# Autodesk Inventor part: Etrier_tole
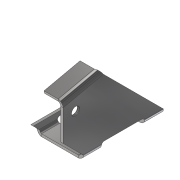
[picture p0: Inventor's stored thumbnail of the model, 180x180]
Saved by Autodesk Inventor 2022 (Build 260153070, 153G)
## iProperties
Created: 2018-06
Part Number: Etrier_tole
Material: Acier inoxydable
Document SubType Name: Tôle
Designer: Fabian Perrée
Density: 8 g/cm^3
Sheet Metal Rule: Par défaut_mm
Appearance: Semi-poli
Flat Pattern Width: 6.40181 cm
Flat Pattern Length: 9.4026 cm
Flat Pattern Area: 60.1936 cm^2
Sheet Metal Width: 64,018 mm
Sheet Metal Length: 94,026 mm
Sheet Metal Area: 6019,365 mm^2
Mass: 45.3586 g
Surface Area: 83.174 cm^2
Volume: 5.66982 cm^3
Author: Fabian Perrée
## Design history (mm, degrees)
node "Face1"
  sketch "Esquisse1"
    geometry: L1 (-12.5, 24)-(12.5, 24); L2 (12.5, 24)-(12.5, -24); L3 (12.5, -24)-(-12.5, -24); L4 (-12.5, -24)-(-12.5, 24); L5 (-12.5, 24)-(12.5, -24); L6 (12.5, 24)-(-12.5, -24); C1 r 3 at (0, 18.5); C2 r 3 at (0, -18.5); 3 further points
    constraints: 12 end point, 4 midpoint, 2 centre point, 2 parallel, 2 vertical alignment, 1 equal radius, 1 horizontal, 1 perpendicular
    dimensions: "d0" = 25 distance of L2.end L3.end; "d1" = 48 distance of L1.end L2.end; "d31" = 5.5 distance from line of L1 C1.centre (= d43); "d32" = 6 diameter of C1; "d43" = 5.5 distance from line of L3 C2.centre
node "Face2"
  sketch "Esquisse2"
    geometry: L1 (0, 0)-(0, 1.5) reference; L2 (48, 0)-(0, 0) reference; L3 (48, 0)-(48, 1.5) reference; L4 (0, 1.5)-(0, 3); L5 (0, 3)-(-12, 15); L6 (-12, 15)-(-12, 36.58); L7 (7, 3.333)-(7, -2.476); L8 (-12, 36.58)-(9.626, 41.374); L9 (48, 1.5)-(48, 3); L10 (48, 3)-(9.626, 41.374); C1 r 2.5 at (-4.5, 28); 2 further points
    constraints: 14 end point, 3 vertical, 1 centre point, 1 coincident, 1 parallel
    dimensions: "d3" = 3 distance from line of L2 L4.end; "d6" = 45 deg angle of L5 L6; "d7" = 28 distance from line of L2 point (-4.5, 28); "d8" = 7 distance between parallel lines of L4 L7; "d9" = 11.5 distance from line of point (-4.5, 28) L7; "d10" = 10 distance from line of point (-4.5, 28) L8; "d11" = 12.5 deg angle of L2 L8; "d12" = 3 distance from line of L2 L9.end; "d13" = 45 deg angle of L2 L10; "d14" = 5 diameter of C1; "d40" = 12 horizontal distance of L5.end L4.end
mirror "Symétrie1"
node "Bord tombé1"
sketch "Esquisse4"
  geometry: L1 (0, 0)-(48, 0) reference; L2 (11, 0)-(37, 0); L3 (37, 0)-(37, 2.5); L4 (35.5, 4)-(12.5, 4); L5 (11, 2.5)-(11, 0); L6 (2.5, 1.5)-(8.5, 1.5) reference; L7 (8.5, 0)-(2.5, 0) reference; L8 (0, 1.5)-(48, 1.5) reference; L9 (8.5, 0)-(2.5, 0) reference; L10 (45.5, 0)-(39.5, 0) reference; L11 (5.5, 0)-(5.5, -3.35); L12 (42.5, 0)-(42.5, -3.35); A1 r 1.5 centre (12.5, 2.5) between (12.5, 4) and (11, 2.5); A2 r 1.5 centre (35.5, 2.5) between (37, 2.5) and (35.5, 4); 3 further points
  constraints: 12 end point, 5 point on line, 4 point on circle, 4 tangent, 2 centre point, 2 midpoint, 2 parallel, 2 vertical, 1 equal radius, 1 horizontal, 1 perpendicular
  dimensions: "d35" = 1.5 radius of A1; "d36" = 4 distance between parallel lines of L2 L4; "d44" = 5.5 distance between parallel lines of L5 L11; "d45" = 5.5 distance between parallel lines of L3 L12 (= d44)
extrude "Extrusion1" cut sketch "Esquisse4" extent not by distance; stored distance "d37" = 10; taper "d38" = 0 deg
feature "Filetage1" dims "d46" = 3, "d47" = 0
sketch "Esquisse5"
  geometry: L1 (43.946, -41.715)-(6.496, -41.715); L2 (6.496, -41.715)-(6.496, 46.634); L3 (6.496, 46.634)-(43.946, 46.634); L4 (43.946, 46.634)-(43.946, -41.715); 1 further point
  constraints: 8 end point, 2 parallel, 1 horizontal, 1 perpendicular
extrude "Extrusion2" cut sketch "Esquisse5" distance "d41" = 20; taper "d42" = 0 deg
node "Solide1"
feature "Plaque1" dims "d2" = 1.5 (= Epaisseur)
feature "Plaque2" dims "d2" = 1.5 (= Epaisseur), "d15" = 1.5 (= RayonPli), "d16" = 1.5 (= LargeurGrugeage), "d18" = 3 (= RestesMinimum)
feature "Pli1" dims "d2" = 1.5 (= Epaisseur), "d15" = 1.5 (= RayonPli), "d16" = 1.5 (= LargeurGrugeage), "d17" = 0.75 (= ProfondeurGrugeage), "d18" = 3 (= RestesMinimum), "d19" = 1.5 (= Rayondetransition), "JeuJointure" = 0.01
sketch "Esquisse3"
  geometry: L1 (11.5, 0)-(11.5, 22.151); L2 (11.5, 22.151)-(0, 22.151); 1 other entity
  constraints: 4 end point, 4 other
feature "Plaque3" dims "d2" = 1.5 (= Epaisseur), "d20" = 1.5 (= LargeurGrugeage), "d21" = 0.75 (= ProfondeurGrugeage), "d22" = 3 (= RestesMinimum), "d23" = 1.5 (= Rayondetransition), "d24" = 11.5, "d25" = 90 deg, "d26" = 1.5 (= RayonPli), "d27" = 6 (= TailleGrugeage), "d28" = 1.5 (= TailleJeu), "d29" = 1.5 (= TailleRayonJacobi), "JeuJointure" = 0.01
feature "Pli2" dims "d2" = 1.5 (= Epaisseur), "d20" = 1.5 (= LargeurGrugeage), "d21" = 0.75 (= ProfondeurGrugeage), "d22" = 3 (= RestesMinimum), "d23" = 1.5 (= Rayondetransition), "d24" = 11.5, "d25" = 90 deg, "d26" = 1.5 (= RayonPli), "JeuJointure" = 0.01
feature "Coin1" dims "d24" = 11.5, "d25" = 90 deg, "d27" = 6 (= TailleGrugeage), "d28" = 1.5 (= TailleJeu), "d29" = 1.5 (= TailleRayonJacobi)
node "Boucle projetée1"
feature "Définition1"
other parameters: "Epaisseur" = 1.5 (derived), "FacteurX" = 4.4, "RayonPli" = 1.5 (= Epaisseur), "LargeurGrugeage" = 1.5 (= Epaisseur), "ProfondeurGrugeage" = 0.75 (= 0.5 x Epaisseur), "TailleGrugeage" = 6 (= 4 x Epaisseur), "RestesMinimum" = 3 (= 2 x Epaisseur), "Rayondetransition" = 1.5 (= RayonPli), "TailleRayonJacobi" = 1.5 (= RayonPli), "TailleJeu" = 1.5 (= Epaisseur), "Epaisseur" = 1.5, "LargeurGrugeage" = 1.5, "ProfondeurGrugeage" = 0.75, "RayonPli" = 1.5, "Rayondetransition" = 1.5, "RestesMinimum" = 3, "TailleGrugeage" = 6, "TailleJeu" = 1.5, "TailleRayonJacobi" = 1.5
